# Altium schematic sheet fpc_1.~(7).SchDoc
size A; SheetNumber: 1; SheetTotal: 1
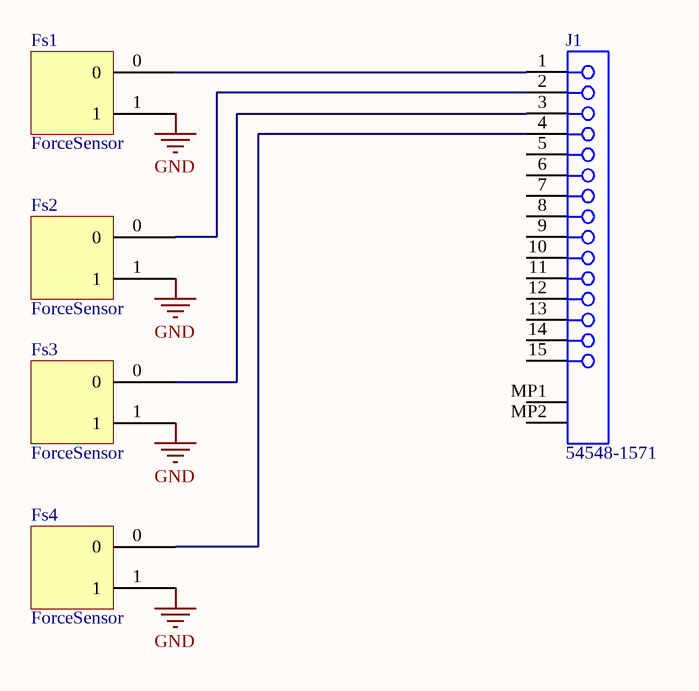
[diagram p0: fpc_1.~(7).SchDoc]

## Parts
Fs1  ForceSensor  [sensor_connector]
Fs2  ForceSensor  [sensor_connector]
Fs3  ForceSensor  [sensor_connector]
Fs4  ForceSensor  [sensor_connector]
J1  54548-1571  [MOLX-54548-1571]

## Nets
GND: Fs1.1 Fs2.1 Fs3.1 Fs4.1
NetFs1_0: Fs1.0 J1.1
NetFs2_0: Fs2.0 J1.2
NetFs3_0: Fs3.0 J1.3
NetFs4_0: Fs4.0 J1.4

Not connected (* = marked no-connect by the designer): J1 5 6 7 8 9 10 11 12 13 14 15 MP1 MP2

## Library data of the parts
J1 = CMP-1241-00549-1: 0.5 mm Pitch Easy-On(TM) Type FPC Connector, 1.2 mm Mated Height, Right Angle, ZIF, SMT, Bottom Contact, 15 Circuits, -20 to 85 degC, ELV and RoHS Compliant, Tape and Reel; Manufacturer: Molex; Stackable: No; Current (Max per Contact): 0.5A; Mated Height: 1.20mm; Entry Angle: 90degrees Angle; Polarized to PCB: Yes; Material - Plating Mating: Gold; Durability (mating cycles max): 20; Circuits (Loaded): 15; Material - Plating Termination: Tin; Material - Metal: Phosphor Bronze; Pitch - Mating Interface: 0.50mm; Voltage (Max): 50V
